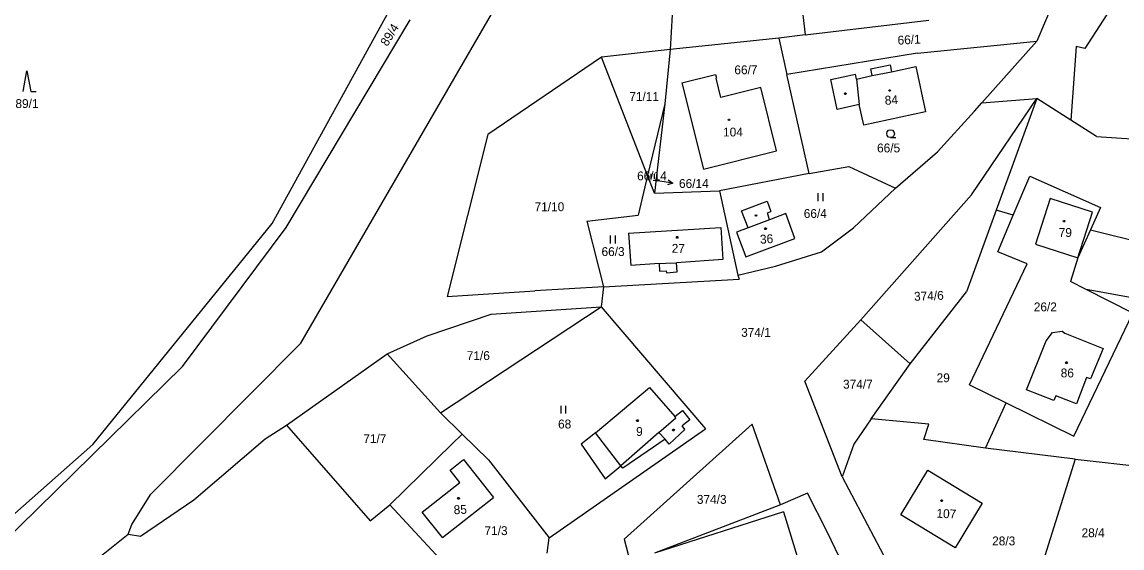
# Model space of a CAD drawing. Extents: x -811039 to -805820, y -1161436 to -1155864.
# Drawn here: x -806771.7 to -806560.9, y -1158236.2 to -1158135.5 of the extents above; entities that cross this region are included whole.
import ezdxf

# ---------------------------------------------------------------- set-up
doc = ezdxf.new("R2010")
doc.units = 0
for name, color, linetype in [('Default', 7, 'Continuous'), ('Hranice parcel', 7, 'Continuous'), ('Parcelní čísla', 7, 'Continuous'), ('Pop  PČ popisy', 7, 'Continuous'), ('Vnitřní kresba', 7, 'Continuous'), ('Značky budov', 7, 'Continuous'), ('Značky kultur', 7, 'Continuous')]:
    doc.layers.add(name, color=color, linetype=linetype)

# ---------------------------------------------------------------- blocks, each defined once
blk = doc.blocks.new('304')
at = {"layer": 'Default'}
blk.add_lwpolyline([(0, 0), (-0.38, 0.1), (-0.65, 0.37), (-0.75, 0.74), (-0.65, 1.11), (-0.38, 1.38), (-0.01, 1.48), (0.36, 1.38), (0.63, 1.11), (0.73, 0.73), (0.63, 0.35), (0.36, 0.08), (-0.02, -0.02), (0.98, -0.02)], dxfattribs=at)
blk = doc.blocks.new('306')
at = {"layer": 'Default'}
for p, q in [((-0.5, 1.5), (-0.5, 0)), ((0.5, 0), (0.5, 1.5))]:
    blk.add_line(p, q, dxfattribs=at)
blk = doc.blocks.new('308')
at = {"layer": 'Default'}
blk.add_lwpolyline([(-0.75, 0), (0, 4), (0.75, 0), (1.75, 0)], dxfattribs=at)
blk = doc.blocks.new('10292')
at = {"layer": 'Default'}
blk.add_line((0, 3), (0, 0), dxfattribs=at)
blk.add_lwpolyline([(-0.5, 2), (0, 3), (0.5, 2)], dxfattribs=at)
blk = doc.blocks.new('402')
at = {"layer": 'Default'}
blk.add_lwpolyline([(0.09, 0.15), (0.18, 0), (0.09, -0.15), (-0.09, -0.15), (-0.18, 0), (-0.09, 0.15), (0.09, 0.15)], dxfattribs=at)

msp = doc.modelspace()

# ---------------------------------------------------------------- linework, layer by layer
at = {"layer": 'Hranice parcel'}
for p, q in [((-806625.5, -1158104.42), (-806621.6, -1158137.92)), ((-806723.74, -1158174.06), (-806693.13, -1158118.44)), ((-806646.33, -1158121.28), (-806647.48, -1158140.75)), ((-806558.78, -1158126.18), (-806568.02, -1158140.53)), ((-806718.26, -1158196.99), (-806677.82, -1158127.15)), ((-806574.25, -1158132.24), (-806577.2, -1158139.11)), ((-806721.04, -1158174.85), (-806697.27, -1158135.03)), ((-806621.6, -1158137.92), (-806597.92, -1158135.1)), ((-806626.66, -1158138.55), (-806647.48, -1158140.75)), ((-806621.6, -1158137.92), (-806626.66, -1158138.55)), ((-806626.66, -1158138.55), (-806625.14, -1158145.51)), ((-806600.08, -1158141.46), (-806577.2, -1158139.11)), ((-806587.74, -1158150.92), (-806577.2, -1158139.11)), ((-806647.48, -1158140.75), (-806660.66, -1158142.19)), ((-806647.48, -1158140.75), (-806648.51, -1158151.16)), ((-806569.67, -1158140.13), (-806570.68, -1158154.28)), ((-806568.02, -1158140.53), (-806569.67, -1158140.13)), ((-806660.66, -1158142.19), (-806682.39, -1158156.98)), ((-806651.8, -1158164.84), (-806660.66, -1158142.19)), ((-806600.08, -1158141.46), (-806625.14, -1158145.51)), ((-806645.27, -1158147.12), (-806638.76, -1158145.49)), ((-806638.76, -1158145.49), (-806638.59, -1158146.19)), ((-806620.86, -1158164.46), (-806625.14, -1158145.51)), ((-806616.67, -1158146.5), (-806611.94, -1158145.48)), ((-806611.75, -1158146.41), (-806611.94, -1158145.48)), ((-806609.04, -1158144.44), (-806605.35, -1158143.69)), ((-806608.8, -1158145.74), (-806609.04, -1158144.44)), ((-806605.35, -1158143.69), (-806605.07, -1158144.98)), ((-806605.07, -1158144.98), (-806600.43, -1158143.97)), ((-806600.43, -1158143.97), (-806598.53, -1158152.7)), ((-806645.27, -1158147.12), (-806641.11, -1158163.62)), ((-806638.59, -1158146.19), (-806638.69, -1158146.21)), ((-806637.77, -1158149.94), (-806638.69, -1158146.21)), ((-806615.49, -1158152.21), (-806616.67, -1158146.5)), ((-806611.75, -1158146.41), (-806608.8, -1158145.74)), ((-806630.11, -1158148.03), (-806637.77, -1158149.94)), ((-806627.08, -1158160.11), (-806630.11, -1158148.03)), ((-806648.51, -1158151.16), (-806651.8, -1158164.84)), ((-806648.51, -1158151.16), (-806650.46, -1158168.28)), ((-806611.24, -1158151.25), (-806615.49, -1158152.21)), ((-806610.39, -1158155.24), (-806611.24, -1158151.25)), ((-806589.71, -1158168.58), (-806577.19, -1158150.1)), ((-806589.16, -1158152.51), (-806587.74, -1158150.92)), ((-806587.74, -1158150.92), (-806577.19, -1158150.1)), ((-806577.19, -1158150.1), (-806584.99, -1158171.53)), ((-806570.68, -1158154.28), (-806577.19, -1158150.1)), ((-806598.53, -1158152.7), (-806610.39, -1158155.24)), ((-806596.26, -1158160.32), (-806589.16, -1158152.51)), ((-806565.79, -1158157.41), (-806570.68, -1158154.28)), ((-806682.39, -1158156.98), (-806690.22, -1158188.05)), ((-806565.79, -1158157.41), (-806554.8, -1158158.09)), ((-806641.11, -1158163.62), (-806627.08, -1158160.11)), ((-806604.3, -1158167.3), (-806596.26, -1158160.32)), ((-806620.86, -1158164.46), (-806638, -1158167.77)), ((-806620.86, -1158164.46), (-806613.26, -1158163.16)), ((-806613.26, -1158163.16), (-806604.3, -1158167.3)), ((-806651.8, -1158164.84), (-806653.63, -1158172.45)), ((-806650.46, -1158168.28), (-806651.8, -1158164.84)), ((-806581.74, -1158172.46), (-806578.57, -1158164.97)), ((-806578.57, -1158164.97), (-806565.02, -1158170.97)), ((-806650.46, -1158168.28), (-806638, -1158167.77)), ((-806638, -1158167.77), (-806634.51, -1158183.94)), ((-806604.3, -1158167.3), (-806612.34, -1158174.92)), ((-806610.94, -1158192.5), (-806589.71, -1158168.58)), ((-806633.81, -1158171.63), (-806628.89, -1158169.81)), ((-806628.89, -1158169.81), (-806628.2, -1158171.77)), ((-806574.65, -1158169.26), (-806577.5, -1158178.04)), ((-806566.53, -1158171.88), (-806574.65, -1158169.26)), ((-806663.42, -1158173.62), (-806653.63, -1158172.45)), ((-806632.51, -1158174.87), (-806633.81, -1158171.63)), ((-806628.81, -1158171.99), (-806628.2, -1158171.77)), ((-806628.42, -1158173.33), (-806628.81, -1158171.99)), ((-806625.31, -1158172.15), (-806628.42, -1158173.33)), ((-806623.58, -1158176.91), (-806625.31, -1158172.15)), ((-806584.99, -1158171.53), (-806590.67, -1158187.16)), ((-806581.74, -1158172.46), (-806584.99, -1158171.53)), ((-806584.71, -1158179.46), (-806581.74, -1158172.46)), ((-806569.37, -1158180.66), (-806566.53, -1158171.88)), ((-806565.02, -1158170.97), (-806566.96, -1158175.3)), ((-806758.12, -1158216.37), (-806723.74, -1158174.06)), ((-806740.96, -1158201.43), (-806721.04, -1158174.85)), ((-806663.42, -1158173.62), (-806661.2, -1158182.44)), ((-806655.48, -1158175.94), (-806637.79, -1158174.85)), ((-806637.79, -1158174.85), (-806637.37, -1158180.94)), ((-806632.51, -1158174.87), (-806634.77, -1158175.72)), ((-806618.45, -1158179.46), (-806612.34, -1158174.92)), ((-806655.48, -1158175.94), (-806654.99, -1158182.11)), ((-806634.77, -1158175.72), (-806633.01, -1158180.44)), ((-806633.01, -1158180.44), (-806623.58, -1158176.91)), ((-806566.96, -1158175.3), (-806569.37, -1158180.66)), ((-806566.96, -1158175.3), (-806533.49, -1158183.62)), ((-806577.5, -1158178.04), (-806569.37, -1158180.66)), ((-806637.37, -1158180.94), (-806646.27, -1158181.59)), ((-806627.29, -1158182.21), (-806618.45, -1158179.46)), ((-806579.07, -1158181.81), (-806584.71, -1158179.46)), ((-806569.37, -1158180.66), (-806570.79, -1158185.17)), ((-806661.2, -1158182.44), (-806660.25, -1158186.2)), ((-806649.57, -1158181.75), (-806654.99, -1158182.11)), ((-806649.57, -1158181.75), (-806649.53, -1158183.19)), ((-806649.53, -1158183.19), (-806648.24, -1158183.14)), ((-806648.24, -1158183.14), (-806648.19, -1158183.48)), ((-806648.19, -1158183.48), (-806646.13, -1158183.34)), ((-806646.13, -1158183.34), (-806646.27, -1158181.59)), ((-806634.51, -1158183.94), (-806627.29, -1158182.21)), ((-806590.13, -1158204.94), (-806579.07, -1158181.81)), ((-806660.25, -1158186.2), (-806634.28, -1158184.71)), ((-806634.51, -1158183.94), (-806634.28, -1158184.71)), ((-806567.76, -1158186.7), (-806570.79, -1158185.17)), ((-806690.22, -1158188.05), (-806673.44, -1158186.95)), ((-806660.25, -1158186.2), (-806673.44, -1158186.95)), ((-806660.25, -1158186.2), (-806660.73, -1158190.04)), ((-806601.46, -1158200.93), (-806590.67, -1158187.16)), ((-806535.97, -1158192.47), (-806567.76, -1158186.7)), ((-806558.81, -1158191.24), (-806567.76, -1158186.7)), ((-806694.06, -1158195.61), (-806681.77, -1158191.44)), ((-806691.48, -1158210.33), (-806660.73, -1158190.04)), ((-806681.77, -1158191.44), (-806660.73, -1158190.04)), ((-806660.73, -1158190.04), (-806640.69, -1158213.39)), ((-806570.15, -1158214.79), (-806558.81, -1158191.24)), ((-806621.66, -1158204.29), (-806610.94, -1158192.5)), ((-806610.94, -1158192.5), (-806601.46, -1158200.93)), ((-806701.73, -1158199.05), (-806694.06, -1158195.61)), ((-806575.43, -1158196.54), (-806574.21, -1158194.95)), ((-806574.21, -1158194.95), (-806572.39, -1158194.67)), ((-806572.39, -1158194.67), (-806571.82, -1158195.06)), ((-806571.82, -1158195.06), (-806564.52, -1158198.01)), ((-806746.97, -1158225.93), (-806718.26, -1158196.99)), ((-806579.19, -1158205.91), (-806575.43, -1158196.54)), ((-806564.52, -1158198.01), (-806566.95, -1158203.82)), ((-806720.99, -1158212.66), (-806701.73, -1158199.05)), ((-806701.73, -1158199.05), (-806691.48, -1158210.33)), ((-806775.62, -1158235.5), (-806740.96, -1158201.43)), ((-806608.94, -1158211.47), (-806601.46, -1158200.93)), ((-806614.52, -1158222.57), (-806621.66, -1158204.29)), ((-806567.68, -1158203.57), (-806569.64, -1158208.59)), ((-806566.95, -1158203.82), (-806567.68, -1158203.57)), ((-806661.77, -1158214.18), (-806651.42, -1158205.5)), ((-806651.42, -1158205.5), (-806646.58, -1158211.03)), ((-806590.13, -1158204.94), (-806583.06, -1158208.43)), ((-806573.94, -1158207.94), (-806579.19, -1158205.91)), ((-806587.07, -1158217.11), (-806583.06, -1158208.43)), ((-806583.06, -1158208.43), (-806570.15, -1158214.79)), ((-806573.6, -1158207.07), (-806573.94, -1158207.94)), ((-806569.64, -1158208.59), (-806573.6, -1158207.07)), ((-806691.48, -1158210.33), (-806687.32, -1158214.39)), ((-806646.58, -1158211.03), (-806645.13, -1158209.88)), ((-806645.13, -1158209.88), (-806643.73, -1158211.67)), ((-806725.06, -1158215.32), (-806720.99, -1158212.66)), ((-806720.99, -1158212.66), (-806704.99, -1158231.03)), ((-806631.74, -1158212.47), (-806656.32, -1158234.5)), ((-806643.73, -1158211.67), (-806645.19, -1158212.83)), ((-806644.67, -1158213.5), (-806645.19, -1158212.83)), ((-806626.33, -1158227.96), (-806631.74, -1158212.47)), ((-806608.94, -1158211.47), (-806612.29, -1158216.31)), ((-806597.93, -1158212.53), (-806608.94, -1158211.47)), ((-806598.86, -1158215.46), (-806597.93, -1158212.53)), ((-806689.31, -1158216.34), (-806687.32, -1158214.39)), ((-806687.32, -1158214.39), (-806682.28, -1158219.32)), ((-806670.66, -1158234.29), (-806640.69, -1158213.39)), ((-806661.77, -1158214.18), (-806664.55, -1158216.31)), ((-806644.67, -1158213.5), (-806647.64, -1158216.31)), ((-806777.52, -1158233.56), (-806758.12, -1158216.37)), ((-806738.78, -1158227.02), (-806725.06, -1158215.32)), ((-806701.18, -1158227.97), (-806689.31, -1158216.34)), ((-806664.55, -1158216.31), (-806659.95, -1158223)), ((-806648.46, -1158215.37), (-806656.52, -1158220.93)), ((-806647.64, -1158216.31), (-806648.46, -1158215.37)), ((-806612.29, -1158216.31), (-806614.52, -1158222.57)), ((-806587.07, -1158217.11), (-806598.86, -1158215.46)), ((-806569.88, -1158219.21), (-806587.07, -1158217.11)), ((-806689.66, -1158221.29), (-806687.05, -1158219.25)), ((-806687.05, -1158219.25), (-806681.35, -1158226.55)), ((-806682.28, -1158219.32), (-806670.66, -1158234.29)), ((-806569.88, -1158219.21), (-806579.62, -1158250.35)), ((-806569.88, -1158219.21), (-806553.85, -1158221)), ((-806687.79, -1158223.66), (-806689.66, -1158221.29)), ((-806659.95, -1158223), (-806656.92, -1158220.46)), ((-806656.52, -1158220.93), (-806656.92, -1158220.46)), ((-806603.29, -1158229.88), (-806598.12, -1158221.34)), ((-806598.12, -1158221.34), (-806587.68, -1158227.66)), ((-806614.52, -1158222.57), (-806600.61, -1158248.81)), ((-806695.01, -1158229.34), (-806687.79, -1158223.66)), ((-806750.61, -1158231.75), (-806746.97, -1158225.93)), ((-806749, -1158233.96), (-806738.78, -1158227.02)), ((-806691.11, -1158234.24), (-806681.35, -1158226.55)), ((-806621.17, -1158225.74), (-806626.33, -1158227.96)), ((-806617.42, -1158233.13), (-806621.17, -1158225.74)), ((-806587.68, -1158227.66), (-806592.88, -1158236.19)), ((-806704.99, -1158231.03), (-806701.18, -1158227.97)), ((-806701.18, -1158227.97), (-806684.08, -1158246.35)), ((-806691.11, -1158234.24), (-806695.01, -1158229.34)), ((-806626.33, -1158227.96), (-806650.49, -1158237.2)), ((-806625.78, -1158229.31), (-806650.49, -1158237.2)), ((-806625.78, -1158229.31), (-806618.07, -1158254.33)), ((-806592.88, -1158236.19), (-806603.29, -1158229.88)), ((-806751.34, -1158233.56), (-806750.61, -1158231.75)), ((-806766.34, -1158245.5), (-806751.34, -1158233.56)), ((-806751.34, -1158233.56), (-806749, -1158233.96)), ((-806611.64, -1158244.97), (-806617.42, -1158233.13)), ((-806671.05, -1158237.22), (-806670.66, -1158234.29)), ((-806656.32, -1158234.5), (-806655.17, -1158238.94))]:
    msp.add_line(p, q, dxfattribs=at)
at = {"layer": 'Pop  PČ popisy'}
msp.add_line((-806650.72, -1158165.79), (-806649.91, -1158165.9), dxfattribs=at)
at = {"layer": 'Vnitřní kresba'}
for p, q in [((-806608.8, -1158145.74), (-806605.07, -1158144.98)), ((-806611.75, -1158146.41), (-806611.24, -1158151.25)), ((-806628.42, -1158173.33), (-806632.51, -1158174.87)), ((-806649.57, -1158181.75), (-806648.29, -1158181.69)), ((-806648.29, -1158181.69), (-806646.27, -1158181.59)), ((-806649.62, -1158214.09), (-806646.38, -1158211.26)), ((-806646.38, -1158211.26), (-806646.58, -1158211.03)), ((-806656.92, -1158220.46), (-806661.77, -1158214.18)), ((-806649.62, -1158214.09), (-806656.92, -1158220.46)), ((-806648.46, -1158215.37), (-806649.62, -1158214.09))]:
    msp.add_line(p, q, dxfattribs=at)

# ---------------------------------------------------------------- block references
at = {"layer": 'Pop  PČ popisy', "rotation": -97.98640000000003}
msp.add_blockref('10292', (-806649.91, -1158165.9), dxfattribs=at)
at = {"layer": 'Značky budov'}
for p in [(-806613.91, -1158149.19), (-806605.42, -1158148.58), (-806636.2, -1158154.2), (-806631.02, -1158172.53), (-806629.2, -1158175.03), (-806571.99, -1158173.61), (-806646.14, -1158176.69), (-806571.53, -1158200.7), (-806653.75, -1158211.83), (-806646.86, -1158213.62), (-806688.03, -1158226.72), (-806595.45, -1158227.17)]:
    msp.add_blockref('402', p, dxfattribs=at)
at = {"layer": 'Značky kultur'}
for name, p in [('308', (-806770.74, -1158148.79)), ('304', (-806605.23, -1158157.59)), ('306', (-806618.66, -1158169.75)), ('306', (-806658.48, -1158177.87)), ('306', (-806667.94, -1158210.48))]:
    msp.add_blockref(name, p, dxfattribs=at)
at = {"layer": 'Značky kultur', "xscale": 0.67, "yscale": 0.67}
msp.add_blockref('306', (-806650.84, -1158165.53), dxfattribs=at)

# ---------------------------------------------------------------- texts
at = {"layer": 'Parcelní čísla'}
for s, rotation, p in [('89/4', 58.213, (-806701.69, -1158140.24)), ('66/1', 2.865, (-806603.86, -1158139.81)), ('84', 3.896, (-806606.3, -1158151.33)), ('36', 3.667, (-806630.21, -1158177.95)), ('66/3', 0.172, (-806660.63, -1158180.3)), ('27', 359.073, (-806647.2, -1158179.66)), ('374/6', 2.292, (-806600.71, -1158188.88)), ('85', 2.578, (-806688.92, -1158229.76)), ('107', 357.354, (-806596.48, -1158230.41))]:
    msp.add_text(s, height=1.7, rotation=rotation, dxfattribs=at).set_placement(p)
for s, p in [('66/7', (-806635.18, -1158145.47)), ('71/11', (-806655.31, -1158150.58)), ('89/1', (-806772.94, -1158151.94)), ('104', (-806637.34, -1158157.39)), ('66/5', (-806607.83, -1158160.44)), ('66/14', (-806653.81, -1158165.79)), ('66/14', (-806645.79, -1158167.25)), ('71/10', (-806673.46, -1158171.7)), ('66/4', (-806621.88, -1158173)), ('79', (-806573.02, -1158176.63)), ('26/2', (-806577.8, -1158190.89)), ('374/1', (-806633.88, -1158195.77)), ('71/6', (-806686.46, -1158200.22)), ('86', (-806572.64, -1158203.54)), ('374/7', (-806614.35, -1158205.7)), ('29', (-806596.42, -1158204.47)), ('68', (-806668.96, -1158213.32)), ('9', (-806654, -1158214.76)), ('71/7', (-806706.28, -1158216.13)), ('374/3', (-806642.36, -1158227.76)), ('71/3', (-806683.06, -1158233.75)), ('28/3', (-806585.78, -1158235.72)), ('28/4', (-806568.64, -1158234.15))]:
    msp.add_text(s, height=1.7, dxfattribs=at).set_placement(p)

doc.saveas('drawing.dxf')
